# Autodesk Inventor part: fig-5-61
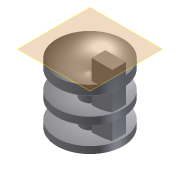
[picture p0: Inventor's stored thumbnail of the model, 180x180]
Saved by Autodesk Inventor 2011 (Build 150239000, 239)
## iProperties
Created: 2004-05
Part Number: fig-5-61
Document SubType Name: Modeling
Designer: CADCIM Technologies
Manufacturer: Standard
Standards Organization: Custom
Density: 1 g/cm^3
Author: CADCIM Technologies
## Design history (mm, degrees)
sketch "Sketch1"
  geometry: L1 (0.098, 22.743)-(0.098, 0.516); L2 (-3.621, 19.305)-(-3.621, 13.061); L3 (-3.621, 10.379)-(-3.621, 3.25); L4 (-3.664, 0.516)-(0.098, 0.516); L5 (-13.694, 4.7)-(-13.694, 1.836); L6 (-13.694, 26.851)-(-13.694, 23.014); L7 (-13.694, 15.335)-(-13.694, 12.343); A1 r 10.546 centre (-4.597, 32.185) between (-13.694, 26.851) and (0.098, 22.743); A2 r 21.828 centre (-4.597, 32.185) between (-13.694, 12.343) and (-3.621, 10.379); A3 r 12.918 centre (-4.597, 32.185) between (-13.694, 23.014) and (-3.621, 19.305); A4 r 19.149 centre (-4.597, 32.185) between (-13.694, 15.335) and (-3.621, 13.061); A5 r 28.952 centre (-4.597, 32.185) between (-13.694, 4.7) and (-3.621, 3.25); A6 r 31.683 centre (-4.597, 32.185) between (-13.694, 1.836) and (-3.664, 0.516)
  constraints: 14 end point, 12 point on circle, 6 centre point, 4 perpendicular, 2 parallel, 1 vertical
revolve "Revolution1" sketch "Sketch1" stored, may be unused: angle "d0" = 90 deg
workplane "Work Plane1"
sketch "Sketch2"
  geometry: L1 (3.408, -2.846)-(12.06, -2.846); L2 (12.06, -2.846)-(12.06, 2.873); L3 (12.06, 2.873)-(3.408, 2.873); L4 (3.408, 2.873)-(3.408, -2.846)
  constraints: 8 end point, 2 parallel, 1 horizontal, 1 perpendicular
extrude "Extrusion3" join sketch "Sketch2" stored distance "d8" = 10; taper "d9" = 0 deg
body "Solid1"
